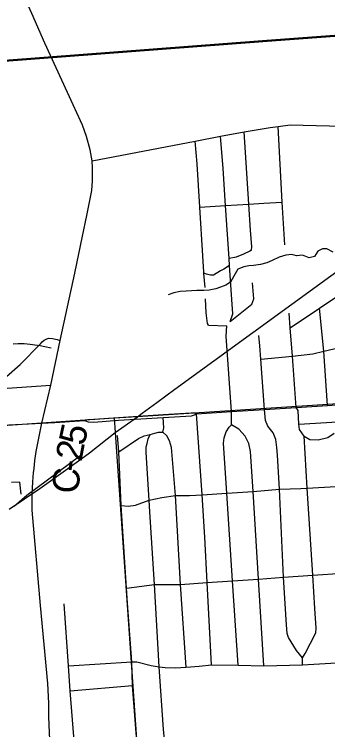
# Model space of a CAD drawing. Extents: x 114604 to 551442, y 316898 to 567001.
# Drawn here: x 179238 to 182780, y 380464 to 388544 of the extents above; entities that cross this region are included whole.
import ezdxf

# ---------------------------------------------------------------- set-up
doc = ezdxf.new("R2010")
doc.units = 0
for name, color, linetype in [('GE_P_Alignment_1000_Bearings', 7, 'Continuous'), ('GE_P_Alignment_1000_Cardinal_Points', 7, 'Continuous'), ('GE_P_Alignment_1000_Stations', 7, 'Continuous'), ('GE_P_Alignment_100_Cardinal_Points', 7, 'Continuous'), ('GE_P_Alignment_500_Bearings', 7, 'Continuous'), ('PM_P_Cells', 7, 'Continuous'), ('PM_P_CL_Double_Solid', 7, 'Continuous')]:
    doc.layers.add(name, color=color, linetype=linetype)

msp = doc.modelspace()

# ---------------------------------------------------------------- linework, layer by layer
at = {"layer": 'GE_P_Alignment_1000_Bearings'}
for q in [(180629.5, 384002.1), (180378.1, 383822)]:
    msp.add_line((180366.1, 383984.7), q, dxfattribs=at)
for points in [[(178330.8, 387966.6), (182044.2, 388248.3), (182398.6, 388274.8), (183366.5, 388347.5), (183771.9, 388378.4), (184067.4, 388400), (184365.4, 388423), (184922.6, 388464.8), (185661.8, 388520.4), (185813.4, 388527.2), (186305.9, 388540), (186559.9, 388535.2), (186840.2, 388519.9), (187098, 388493.1), (187179.5, 388482.3), (187415.1, 388442.5), (187558.4, 388415.6), (187794.6, 388360.8), (188017.8, 388299.3), (188168.2, 388253.2), (188485.4, 388138.6), (188966.4, 387955.8), (189444.6, 387773.5)], [(178331.8, 387953.5), (182045.2, 388235.2), (182399.6, 388261.8), (183367.5, 388334.4), (183772.9, 388365.3), (184068.3, 388387), (184366.4, 388410), (184923.6, 388451.7), (185662.6, 388507.3), (185813.8, 388514), (186305.9, 388526.9), (186559.4, 388522.1), (186839.1, 388506.8), (187096.5, 388480), (187177.6, 388469.3), (187412.8, 388429.6), (187555.7, 388402.8), (187791.4, 388348.1), (188014.2, 388286.7), (188164.1, 388240.7), (188480.9, 388126.3), (188961.8, 387943.6), (189439.9, 387761.3)], [(179180.6, 382953.2), (179525.7, 383187.1), (179816.3, 383394.3), (179991, 383520.5), (180086.4, 383592.5), (180379.3, 383819.2), (180630.6, 383999.3), (180683.6, 384038.4), (180848.3, 384157.7), (181052.7, 384310.2), (183256.9, 385910)], [(180629.5, 384002.1), (191270.2, 384690.2), (191954.5, 384767.5), (195392.5, 385288.4)], [(139976.5, 381530.3), (141701.6, 381686.5), (142931.4, 381776.7), (145058.8, 381883.3), (151605.9, 382247), (160057.2, 382729.4), (166949.7, 383110), (174406.2, 383574.4), (180366.1, 383984.7)], [(180378.1, 383822), (180652.5, 379872.3), (185830.5, 380217.5), (192483.8, 381831.8), (195789.4, 382643.8)], [(179235.5, 382990.4), (179378.5, 383114.4), (179979.6, 383557.8)]]:
    msp.add_lwpolyline(points, dxfattribs=at)
at = {"layer": 'GE_P_Alignment_1000_Cardinal_Points'}
msp.add_lwpolyline([(179314.5, 383125.2), (179301.2, 383261.1), (179207, 383256.3)], dxfattribs=at)
at = {"layer": 'GE_P_Alignment_1000_Stations'}
msp.add_line((179694.9, 383935.2), (180032.5, 383954.8), dxfattribs=at)
for points in [[(181298.4, 384032.2), (181691.8, 384059.4), (182065.9, 384080.5), (182424.3, 384102.5), (182778.8, 384124.6), (182880.3, 384132.1), (183136.1, 384147.5), (183443.2, 384169), (183471.2, 384170.7), (183736.9, 384187.7), (183824.1, 384193.3), (184286.6, 384221.5), (184345.2, 384226.3), (184641.1, 384241.9), (184991.3, 384267.2), (185023.8, 384269.3), (185367.1, 384291.9)], [(180032.5, 383954.8), (180074.1, 383965.8), (180137.7, 383972.3), (180414.9, 383990.9), (180920, 384023), (181238.1, 384043.4), (181273.4, 384041.2), (181298.4, 384032.2)], [(180032.5, 383954.8), (180073.1, 383940.6), (180138.7, 383939.3), (180416, 383958.2), (180921.2, 383990.9), (181239.3, 384010.4), (181273.5, 384019), (181298.4, 384032.2)], [(177622.8, 383794.2), (177781.7, 383807.4), (177948.1, 383818.3), (178113.9, 383829.2), (178442.8, 383851.8), (178804.7, 383877.9), (178825.5, 383879.6), (178950.5, 383888.3), (179175.5, 383905.5), (179550.3, 383926.8), (179694.9, 383935.2)]]:
    msp.add_lwpolyline(points, dxfattribs=at)
at = {"layer": 'GE_P_Alignment_100_Cardinal_Points'}
for p, q in [((181677.6, 385073.2), (181922.1, 385269.3)), ((181433, 385033.5), (181641, 385025.8)), ((178985, 384311.6), (179651.7, 384355.5)), ((179870.3, 380903.5), (180575.6, 380963.4))]:
    msp.add_line(p, q, dxfattribs=at)
for points in [[(182296.6, 385938.8), (182263.9, 386423.3), (182219.1, 387275.5)], [(181919.6, 385881.1), (181923, 385918.7), (181906.9, 386107.8), (181887.8, 386399.4), (181834.4, 387217.1)], [(181380.6, 385633.4), (181367.4, 385816.2), (181333.5, 386364.2), (181303.2, 386855.6), (181281.7, 387111.2)], [(181677.6, 385073.2), (181708.7, 385160.2), (181697.6, 385322.8), (181671.7, 385706.8), (181666.3, 385786.4), (181626.1, 386382.8), (181597.9, 386801.7), (181570.1, 387166.5)], [(181333.5, 386364.2), (181626.1, 386382.8), (181887.8, 386399.4), (182057.1, 386410.2), (182263.9, 386423.3)], [(181919.6, 385881.1), (181898.4, 385867.8), (181827.2, 385833.5), (181743.8, 385802.8), (181666.3, 385786.4)], [(181671.7, 385706.8), (181607.5, 385666), (181568, 385644.8), (181491.1, 385598.2), (181455, 385597.1), (181410.5, 385607.8), (181388.2, 385615.2), (181380.6, 385633.4)], [(181393.4, 385457), (181381.7, 385617.8), (181380.6, 385633.4)], [(181922.1, 385269.3), (181944.5, 385331.3), (181929.5, 385511.9)], [(181433, 385033.5), (181421.1, 385053.6), (181407.8, 385174.1), (181400.6, 385330.6)], [(182356.2, 385001), (182685.8, 385223.2), (182951.9, 385402.5)], [(182424.3, 384102.5), (182380.4, 384681.4), (182356.2, 385001), (182343.6, 385167.2)], [(182778.8, 384124.6), (182735.5, 384740.6), (182685.8, 385223.2)], [(181691.8, 384059.4), (181633.4, 384907.9), (181641, 385025.8)], [(179151.8, 384452.9), (179303.1, 384589.6), (179535.9, 384822.5), (179553.2, 384843.4), (179576.4, 384863.5), (179605.4, 384879.5), (179627, 384886.4), (179669.4, 384884.1), (179721, 384871.2), (179758.1, 384859.8)], [(182065.9, 384080.5), (182022.5, 384649.1), (182013.1, 384798.5), (182001.1, 384916.3)], [(182022.5, 384649.1), (182380.4, 384681.4), (182612, 384709.8), (182735.5, 384740.6), (182911.6, 384779)], [(182058.7, 381186.9), (181997.5, 382165.8), (181935.8, 383153.2), (181907.5, 383605.4), (181887.2, 383697.2), (181847.2, 383779.3), (181776.8, 383859.1), (181693.9, 383906.4), (181691.8, 384059.4)], [(182495.9, 381276.3), (182429.2, 381357.8), (182335.5, 381503.9), (182320.3, 381552.3), (182313.9, 381646.8), (182279.9, 382185.4), (182234.6, 383181.1), (182210.9, 383566.2), (182206.6, 383652.1), (182193.8, 383742.7), (182164, 383817.7), (182103.5, 383891.6), (182077.5, 383956.5), (182065.9, 384080.5)], [(182496.2, 381195.9), (182495.9, 381276.3), (182524.5, 381325.3), (182644.2, 381559.9), (182648.7, 381612.3), (182634.2, 381832.9), (182610.7, 382208.5), (182549.5, 383191.1), (182512.9, 383778.1), (182462.1, 383852.8), (182455.3, 383915.3), (182446.2, 384069), (182424.3, 384102.5)], [(181467.3, 381195.5), (181416.8, 382125.3), (181389.6, 382639.8), (181360.9, 383117.2), (181298.4, 384032.2)], [(182455.3, 383915.3), (182889, 383942.4), (183147.8, 383961.5), (183455, 383979.2)], [(181767.3, 381194.4), (181705.2, 382145.4), (181640.5, 383134.7), (181603.5, 383700.9), (181609.8, 383761.7), (181631.8, 383828.4), (181667.4, 383879.4), (181693.9, 383906.4)], [(180418, 383602.1), (180641.1, 383754.5), (180704.7, 383782.2), (180775.2, 383797.6)], [(181179.7, 381168.9), (181115.7, 382104.3), (181061.4, 383111), (181015.4, 383652.6), (180991.7, 383725.8), (180960.1, 383781.3), (180917.7, 383824.4)], [(182512.9, 383778.1), (182576.4, 383740.8), (182670.6, 383737.1), (182781.3, 383765.3), (182854.1, 383811.7)], [(180654.5, 379873.4), (180629.4, 380235.2), (180575.6, 380963.4), (180568.2, 381231.3), (180516.2, 381894.2), (180505.6, 382061.7), (180446, 382995.3), (180418, 383602.1), (180405.8, 383786.8)], [(180446, 382995.3), (180526, 382989.9), (180608.4, 383000.5), (180763.4, 383055.1), (180906.7, 383085.4), (181061.4, 383111), (181217.9, 383108.3), (181360.9, 383117.2), (181640.5, 383134.7), (181935.8, 383153.2), (182234.6, 383181.1), (182474.6, 383186.8), (182549.5, 383191.1), (182872.3, 383209.7)], [(180505.6, 382061.7), (180821.6, 382102.7), (181115.7, 382104.3), (181416.8, 382125.3), (181705.2, 382145.4), (181997.5, 382165.8), (182279.9, 382185.4), (182610.7, 382208.5), (182946.6, 382232), (183209.2, 382250.2), (183248, 382253), (183558.2, 382274.6), (183856.6, 382295.4), (184003.7, 382305.6), (184067.4, 382347.1), (184143.8, 382447.2), (184177.4, 382491.2), (184241.8, 382575.6), (184267.2, 382598.5), (184382.8, 382660.2), (184411.5, 382671.2), (184437.5, 382673.8)], [(179956, 379827.5), (179870.3, 380903.5), (179851.1, 381185.6), (179803.3, 381885.5)], [(179851.1, 381185.6), (180568.2, 381231.3), (180621.4, 381230.3), (180785.4, 381189.2), (180876.5, 381175.9), (180943.7, 381165.8), (181059.7, 381161.2), (181179.7, 381168.9), (181327.9, 381183.3), (181467.3, 381195.5), (181767.3, 381194.4), (182058.7, 381186.9), (182496.2, 381195.9), (182879, 381219.3), (182977, 381234.3), (183059.4, 381232.7), (183108, 381218.1), (183175.1, 381202.8)]]:
    msp.add_lwpolyline(points, dxfattribs=at)
at = {"layer": 'GE_P_Alignment_500_Bearings'}
for points in [[(179550.3, 383926.8), (179651.7, 384355.5), (179758.1, 384859.8), (179920.9, 385621.1), (180008.1, 386039.5), (180056.7, 386272.7), (180114, 386553.5), (180122.3, 386662), (180122.8, 386727.9), (180122.3, 386809.1), (180118.3, 386888.3), (180095.5, 387012.7), (180055.1, 387165.5), (180009.5, 387291.3), (179838.3, 387662.2), (179584.5, 388219.5), (179436, 388551.5), (178953, 389603.7), (178672.4, 390218.8), (178650, 390268.8)], [(180118.3, 386888.3), (181281.7, 387111.2), (181570.1, 387166.5), (181834.4, 387217.1), (182130.9, 387266.8), (182219.1, 387275.5), (182355.3, 387296.5), (183093.4, 387277.8), (184202.6, 387242.3), (184301.9, 387240.4)], [(180980.8, 379945.5), (180975.3, 380033.4), (180970, 380091.6), (180946.9, 380257.8), (180936.2, 380334.2), (180930.4, 380395.5), (180922.5, 380466.7), (180876.5, 381175.9), (180821.6, 382102.7), (180771.7, 382923.8), (180763.4, 383055.1), (180727.8, 383596.2), (180730.1, 383657.4), (180737.9, 383698.2), (180752.5, 383748.5), (180775.2, 383797.6), (180826.7, 383814.3), (180868.8, 383822.7), (180917.7, 383824.4), (180926.8, 383873.4), (180921.2, 383990.9)], [(179461, 383409.2), (179470.2, 383503.3), (179485.6, 383606.9), (179550.3, 383926.8)], [(179439, 383044.2), (179438.4, 383121.8), (179447.6, 383261.8), (179457, 383367.4), (179461, 383409.2)], [(179628, 380747.8), (179627.9, 380763.3), (179615.8, 380986.5), (179534.6, 381866.8), (179441.7, 382945.4), (179439.2, 383018.4), (179439, 383044.2)], [(179670.5, 379808.1), (179634.8, 380429.3), (179629, 380613.5), (179628, 380747.8)]]:
    msp.add_lwpolyline(points, dxfattribs=at)
at = {"layer": 'PM_P_Cells'}
for points in [[(182843, 385859), (182771.2, 385895.6), (182721.2, 385895.9), (182669, 385870.2), (182632.6, 385808.3), (182570.5, 385794.6), (182494.6, 385823.2), (182428.6, 385815.6), (182374.6, 385832)], [(182374.6, 385832), (182306.6, 385824.4), (182230.4, 385800.8), (182152.1, 385763.3), (182091.9, 385737.6), (182021.7, 385718), (181939.6, 385708.5), (181889.6, 385702.8), (181833.5, 385691.1), (181765.3, 385665.5), (181720.7, 385585.6), (181680.3, 385517.7), (181630.1, 385485.9), (181569.9, 385462.3), (181515.7, 385444.6), (181439.6, 385429), (181381.6, 385425.4), (181301.5, 385423.9), (181239.5, 385422.3), (181179.4, 385418.7), (181113.3, 385413.1), (181041.2, 385397.5), (180977, 385373.9)], [(179226.6, 384823.8), (179282.7, 384825.4), (179348.7, 384825), (179418.7, 384818.5), (179470.7, 384810.2), (179530.6, 384801.8), (179584.6, 384791.4), (179654.5, 384776.9)]]:
    msp.add_lwpolyline(points, dxfattribs=at)

# ---------------------------------------------------------------- texts
at = {"layer": 'PM_P_CL_Double_Solid'}
for s, rotation, p in [('5', 77.83833, (180029.9, 383662.4)), ('2', 79.32134, (179996.1, 383482.8)), ('-', 82.99256, (179981.8, 383365.6)), ('C', 85.72409, (179963.8, 383123.6))]:
    msp.add_text(s, height=300, rotation=rotation, dxfattribs=at).set_placement(p)

doc.saveas('drawing.dxf')
